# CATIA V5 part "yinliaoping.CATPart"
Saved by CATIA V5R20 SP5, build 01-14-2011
Part number: 饮料瓶2
Bounding box of the stored display mesh (mm): x -25 to 25, y -25 to 25.1, z 0 to 110
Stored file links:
  E:\yinliaoping.CATPart
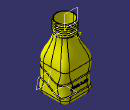
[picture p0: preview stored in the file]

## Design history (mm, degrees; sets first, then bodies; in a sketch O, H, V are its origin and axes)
Set1
  Sketch1 on xy-plane, origin (0, 0, 0), H (1, 0, 0), V (0, 1, 0)
    line L1 (25, 25) -> (25, -25)
    line L2 (25, -25) -> (-25, -25)
    line L3 (-25, -25) -> (-25, 25)
    line L4 (-25, 25) -> (25, 25)
    length L4 = 50
    length L1 = 50
    vertical: L1 V, L3 V
    horizontal: L2 H, L4 H
    equidistance: L1 L3 O, L2 L4 O
  Sketch2 on face of Pad1 from Sketch1.L1, origin (25, 0, 0), H (0, 1, 0), V (0, 0, 1)
    spline S1 through (-36.2456, 11.5397) (-5.4994, 21.8597) (8.3358, 13.7961) (34.0462, 21.22)
  Extrude1: Element1 Sketch2, Lim1 57, Lim2 57
  MultiSel1: CommonCtxFeats ({extract ExtractElem face of Pad1 from Sketch1.L3}; {extract ExtractElem face of Fillet1}; {extract ExtractElem face of Pad1 from Sketch1.L4}; {extract ExtractElem face of Fillet1}; {extract ExtractElem face of Pad1 from Sketch1.L1}; {extract ExtractElem face of Fillet1}; {extract ExtractElem face of Pad1 from Sketch1.L2}; {extract ExtractElem face of Fillet1})
  Sketch3 on face of Pad1 from Sketch1.L1, origin (25, 0, 0), H (0, 1, 0), V (0, 0, 1)
    spline S1 through (-37.6349, 30.3591) (-7.2022, 38.8326) (7.9101, 30.5568) (30.932, 39.331)
  Extrude2: Element1 Sketch3, Lim1 79, Lim2 79
  MultiSel2: CommonCtxFeats ({extract ExtractElem face of Pad1 from Sketch1.L1}; {extract ExtractElem face of Fillet1}; {extract ExtractElem face of Fillet1}; {extract ExtractElem face of Pad1 from Sketch1.L2}; {extract ExtractElem face of Fillet1}; {extract ExtractElem face of Pad1 from Sketch1.L3}; {extract ExtractElem face of Fillet1}; {extract ExtractElem face of Pad1 from Sketch1.L4})
  Join1: Elements ({intersect ToIntersect1 {extract ExtractElem face of Pad1 from Sketch1.L1}, ToIntersect2 Extrude2}; {intersect ToIntersect1 {extract ExtractElem face of Fillet1}, ToIntersect2 Extrude2}; {intersect ToIntersect1 {extract ExtractElem face of Fillet1}, ToIntersect2 Extrude2}; {intersect ToIntersect1 {extract ExtractElem face of Pad1 from Sketch1.L2}, ToIntersect2 Extrude2}; {intersect ToIntersect1 {extract ExtractElem face of Fillet1}, ToIntersect2 Extrude2}; {intersect ToIntersect1 {extract ExtractElem face of Pad1 from Sketch1.L3}, ToIntersect2 Extrude2}; {intersect ToIntersect1 {extract ExtractElem face of Fillet1}, ToIntersect2 Extrude2}; {intersect ToIntersect1 {extract ExtractElem face of Pad1 from Sketch1.L4}, ToIntersect2 Extrude2})
  Join2: Elements ({intersect ToIntersect1 {extract ExtractElem face of Pad1 from Sketch1.L1}, ToIntersect2 Extrude1}; {intersect ToIntersect1 {extract ExtractElem face of Fillet1}, ToIntersect2 Extrude1}; {intersect ToIntersect1 {extract ExtractElem face of Pad1 from Sketch1.L4}, ToIntersect2 Extrude1}; {intersect ToIntersect1 {extract ExtractElem face of Fillet1}, ToIntersect2 Extrude1}; {intersect ToIntersect1 {extract ExtractElem face of Pad1 from Sketch1.L3}, ToIntersect2 Extrude1}; {intersect ToIntersect1 {extract ExtractElem face of Fillet1}, ToIntersect2 Extrude1}; {intersect ToIntersect1 {extract ExtractElem face of Pad1 from Sketch1.L2}, ToIntersect2 Extrude1}; {intersect ToIntersect1 {extract ExtractElem face of Fillet1}, ToIntersect2 Extrude1})
  Plane1: type Normal, Curve Join2, RefPoint vertex [face of MultiSel1 | face of MultiSel1]
  Circle1: type CtrRad, Start 0, End 180, Center vertex [face of MultiSel1 | face of MultiSel1], Support Plane1, Radius 1, FirstDirection (1, 0, 0)
Body1 (main body)
  Pad1: profile Sketch1, direction (0, 0, 1), length 50
  Fillet1: on edge [face of Pad1 from Sketch1.L2 | face of Pad1 from Sketch1.L3]; edge [face of Pad1 from Sketch1.L3 | face of Pad1 from Sketch1.L4]; edge [face of Pad1 from Sketch1.L4 | face of Pad1 from Sketch1.L1]; edge [face of Pad1 from Sketch1.L1 | face of Pad1 from Sketch1.L2]
  Fillet2: radius 8, on start face of Pad1
  Plane2: type Offset, RefPlane end face of Pad1, Offset 40, reversed
  Sketch4 on Plane2, origin (0, 0, 90), H (1, 0, 0), V (0, -1, 0)
    circle A1 centre (0, 0) radius 15
    radius A1 = 15
  Pad2: profile Sketch4, direction (0, 0, 1), length 20
  Sketch5 on end face of Pad1, origin (0, 0, 50), H (1, 0, 0), V (0, 1, 0)
    point P1 (-25, 0)
    distance P1 O = 25
    coincidence: P1 H
  Sketch6 on start face of Pad2, origin (0, 0, 90), H (1, 0, 0), V (0, -1, 0)
    point P1 (-15, 0)
    distance P1 O = 15
    coincidence: P1 H
  Loft1: solid, Sections ({boundary Boundary {extract ExtractElem end face of Pad1}}; {boundary Boundary {extract ExtractElem start face of Pad2}}), StartFace end face of Pad1, EndFace start face of Pad2
  Slot1: profile Circle1, centre curve Join2
  Plane3: type Normal, Curve Join1, RefPoint vertex [face of MultiSel2 | face of MultiSel2]
  Circle2: type CtrRad, Start 0, End 180, Center vertex [face of MultiSel2 | face of MultiSel2], Support Plane3, Radius 1, FirstDirection (1, 0, 0)
  Slot2: profile Circle2, centre curve Join1
  Shell1: ExtOffset 0, Face end face of Pad2, IntOffset 1
  Plane4: type Offset, RefPlane {extract ExtractElem start face of Pad2}, Offset 2
  Sketch7 on Plane4, origin (0, 0, 92), H (1, 0, 0), V (0, 1, 0)
    point P1 (15, 0)
    distance P1 O = 15
    coincidence: P1 H
  Helix1: Direction Z axis, RefPoint Sketch7, Pitch 3, Height 16, TaperAngle 0
  Point1: type OnCurve, Support Helix1, Length 5
  Line1: type PtDir, RefPoint Sketch7, Direction (1, 0, 0), Start 0, End 10
  Connect1: Curve1 Line1, Point1 vertex of Line1, Tension1 1, Curve2 Helix1, Point2 Point1, Tension2 1
  Point2: type OnCurve, Support Connect1, Length -5, RefPoint vertex of Helix1
  Line2: type PtDir, RefPoint vertex of Helix1, Direction (0, 1, 0), Start 0, End 10
  Connect2: Curve1 Line2, Point1 vertex of Line2, Tension1 1, Curve2 Connect1, Point2 Point2, Tension2 1
  Plane5: type Normal, Curve Connect2, RefPoint vertex of Connect2
  Sketch8 on Plane5, origin (0, 2.9904, 0), H (-1, 0, 0), V (0, 0, 1)
    circle A1 centre (7.4827, 107.8792) radius 1
    radius A1 = 1
  Rib1: profile Sketch8, centre curve Connect2
  Body2
    Sketch9 on Plane4, origin (0, 0, 92), H (1, 0, 0), V (0, 1, 0)
      circle A1 centre (0, 0) radius 14
      radius A1 = 14
    Pad3: profile Sketch9, direction (0, 0, 1), length 23, mirrored extent
  Remove1: tool Body2
Body3
  Sketch10 on face of Pad1 from Sketch1.L4, origin (0, 25, 0), H (-1, 0, 0), V (0, 0, 1)
    polyline C1
    polyline C2
    polyline C3
    polyline C4
    polyline C5
    polyline C6
    polyline C7
    polyline C8
    polyline C9
    polyline C10
    polyline C11
  Pad4: profile Sketch10, direction (0, 1, 0), length 0.1, mirrored extent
